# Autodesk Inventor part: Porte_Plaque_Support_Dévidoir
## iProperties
Created: 2009-01
Part Number: Porte_Plaque_Support_Dévidoir
Document SubType Name: Sheet Metal
Designer: claivier
Author: claivier
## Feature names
1. Extrusion1
2. Perçage1 [Hole]
3. Perçage2 [Hole]
4. Extrusion2
5. Perçage3 [Hole]
6. Perçage4 [Hole]
7. Extrusion3
8. Révolution2 [Revolution]
9. Plaque1
10. Pli1
11. Couper1
12. Couper2
13. Couper3
